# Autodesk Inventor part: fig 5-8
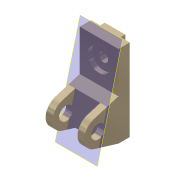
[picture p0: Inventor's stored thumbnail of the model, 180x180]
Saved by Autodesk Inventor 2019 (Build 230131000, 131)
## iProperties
Shininess: 65.0
Angle Display Precision: 2
Document Length Units: 11269
Document Angle Units: 11279
Document Time Units: 11290
Document Mass Units: 11283
Document Length Units Precision: 3
Document Angle Units Precision: 2
Compacted: False
Created: 2001-11
Part Number: fig 5-8
Document SubType Name: Modeling
Designer: Renu Muthoo
Density: 1 g/cm^3
Material: Generic
Appearance: Metal-Titanium (Polished)
Density: 0.0
Volumn: 0.0
Area: 0.0
PropertySet Name: Model Information
Control State: 0
Master: False
Checked Out: False
Author: Renu Muthoo
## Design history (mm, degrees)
node "Sketch1"
sketch "Sketch2"
  geometry: L1 (33.257, 104.664)-(33.257, -75.336); L2 (33.257, -75.336)-(8.257, -75.336); L3 (8.257, -75.336)-(-45.451, -59.045); L4 (-45.451, -1.628)-(8.257, 14.664); L5 (8.257, 14.664)-(8.257, 104.664); L6 (8.257, 104.664)-(33.257, 104.664); C1 r 15 at (-36.743, -30.336); A1 r 30 centre (-36.743, -30.336) between (-45.451, -1.628) and (-45.451, -59.045)
  constraints: 12 end point, 2 centre point, 2 equal length, 2 parallel, 2 point on circle, 2 tangent, 1 coincident, 1 perpendicular, 1 vertical
  dimensions: "d0" = 180 distance of L1.start L1.end; "d1" = 30 radius of A1; "d2" = 25 distance of L5.end L1.start; "d3" = 45 distance from line of L2 A1.centre; "d4" = 70 distance from line of L1 A1.centre; "d5" = 30 diameter of C1
extrude "Extrusion1" new body sketch "Sketch2" distance "d6" = 85; taper "d7" = 0 deg
workplane "Work Plane1"
sketch "Sketch3"
  geometry: L1 (15, 62.364)-(70, 62.364); L2 (70, 62.364)-(70, -52.386); L3 (70, -52.386)-(15, -52.386); L4 (15, -52.386)-(15, 62.364); L5 (0, -45)-(0, -28.708) reference
  constraints: 8 end point, 2 parallel, 1 horizontal, 1 perpendicular
  dimensions: "d8" = 55 distance of L1.start L1.end; "d9" = 15 distance between parallel lines of L5 L4
extrude "Extrusion2" cut sketch "Sketch3" distance "d10" = 50; taper "d11" = 0 deg
sketch "Sketch4"
  geometry: L1 (0, 25)-(85, 25) reference; L2 (0, 0)-(0, 25) reference; L3 (20, 25)-(65, 25); L4 (65, 25)-(65, 35); L5 (65, 35)-(20, 35); L6 (20, 35)-(20, 25)
  constraints: 8 end point, 2 parallel, 1 horizontal, 1 perpendicular, 1 point on line
  dimensions: "d12" = 45 distance of L4.end L5.end; "d13" = 10 distance of L3.end L4.end; "d14" = 20 distance between parallel lines of L2 L6
extrude "Extrusion3" join sketch "Sketch4" stored distance "d15" = 50; taper "d16" = 0 deg
sketch "Sketch5"
  geometry: L1 (85, 0)-(85, 90) reference; L2 (0, 90)-(85, 90) reference; 1 further point
  dimensions: "d17" = 42 distance from line of L2 point (42.5, 48); "d18" = 42.5 distance from line of L1 point (42.5, 48)
hole "Hole1" sketch "Sketch5" at (42.5, 48) diameter "d19" = 20; stored, may be unused: countersink angle "d23" = 82 deg, drill point angle "d25" = 118 deg; dims "d20" = 6, "d21" = 50, "d22" = 10, "d24" = 8
workplane "Work Plane5"
body "Solid1"
